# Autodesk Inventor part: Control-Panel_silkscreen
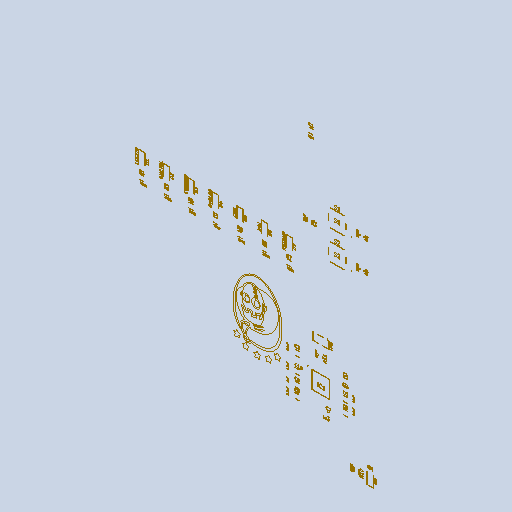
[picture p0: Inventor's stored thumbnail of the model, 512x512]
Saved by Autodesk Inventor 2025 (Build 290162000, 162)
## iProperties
Created: 2026-09
Part Number: Control-Panel_silkscreen
Material: Generic
Document SubType Name: Modeling
Designer: Leonardo
Density: 1 g/cm^3
Appearance: Default
Author: Leonardo
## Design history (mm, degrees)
feature "Composite1"
body "Srf1"
